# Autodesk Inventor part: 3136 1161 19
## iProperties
Shininess: 20.0
Length Units: 11269
Angle Units: 11279
Time Units: 11290
Mass Units: 11283
Length Display Precision: 3
Angle Display Precision: 2
Compacted: True
Created: 2000-11
Part Number: 3136 1161 19
Material: Steel, Mild
Document SubType Name: Modeling
Designer: Joe M
Engineer: Joe M
Density: 0.0
Volumn: 0.0
Area: 0.0
PropertySet Name: Model Information
Control State: 0
Master: False
Checked Out: False
Last Check In By: brpog
Last Check In Date: 2001-02-28
Title: Täcklock kabelledare
Author: Joe M
